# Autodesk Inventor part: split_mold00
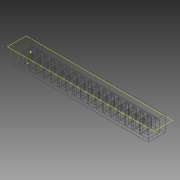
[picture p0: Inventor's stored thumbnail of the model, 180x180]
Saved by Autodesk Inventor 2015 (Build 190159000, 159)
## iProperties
Created: 2015-04
Part Number: split_mold00
Material: Generic
Document SubType Name: Modeling
Designer: sungeun
Density: 1 g/cm^3
Appearance: Default
Author: sungeun
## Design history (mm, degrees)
sketch "Sketch1"
  geometry: L1 (-4, -7.5)-(4, -7.5); L2 (4, -7.5)-(4, 7.5); L3 (4, 7.5)-(-4, 7.5); L4 (-4, 7.5)-(-4, -7.5); L5 (-4, -7.5)-(4, 7.5); L6 (4, -7.5)-(-4, 7.5); 1 further point
  constraints: 12 end point, 2 midpoint, 2 parallel, 1 horizontal, 1 perpendicular
  dimensions: "d0" = 8 distance of L3.end L2.end; "d1" = 15 distance of L2.end L1.end
extrude "Extrusion1" new body sketch "Sketch1" distance "d2" = 15; taper "d3" = 0 deg
sketch "Sketch2"
  geometry: L1 (-3, 5.5)-(3, 5.5); L2 (3, 5.5)-(3, -5.5); L3 (3, -5.5)-(-3, -5.5); L4 (-3, -5.5)-(-3, 5.5); L5 (4, -7.5)-(4, 7.5) reference; L6 (-4, 7.5)-(-4, -7.5) reference; L7 (4, 7.5)-(-4, 7.5) reference; L8 (-4, -7.5)-(4, -7.5) reference; 1 further point
  constraints: 8 end point, 2 parallel, 1 horizontal, 1 perpendicular
  dimensions: "d4" = 1 distance between parallel lines of L5 L2; "d5" = 1 distance between parallel lines of L6 L4; "d6" = 2 distance between parallel lines of L7 L1; "d7" = 2 distance between parallel lines of L8 L3
extrude "Extrusion2" cut sketch "Sketch2" distance "d8" = 13; taper "d9" = 0 deg
sketch "Sketch3"
  geometry: L1 (0, 15)-(-15, 15) reference; L2 (-15, 0)-(-12, 0); L3 (-12, 0)-(-12, 15); L4 (-12, 15)-(-15, 15); L5 (-15, 15)-(-15, 0); L6 (-15, 0)-(-15, 15) reference; 2 further points
  constraints: 8 end point, 2 midpoint, 2 parallel, 1 coincident, 1 horizontal, 1 perpendicular, 1 point on line
  dimensions: "d17" = 3 distance of L2.start L2.end; "d18" = 15 distance of L2.end L3.end
extrude "Extrusion3" join sketch "Sketch3" distance "d11" = 2; taper "d12" = 0 deg
pattern_linear "Rectangular Pattern1"
sketch "Sketch4"
  geometry: L1 (0, 15)-(-12, 15); L2 (-12, 15)-(-12, 0); L3 (-12, 0)-(0, 0); L4 (0, 0)-(0, 15); 1 further point
  constraints: 8 end point, 2 parallel, 1 horizontal, 1 perpendicular
extrude "Extrusion4" join sketch "Sketch4" distance "d19" = 2; taper "d20" = 0 deg
sketch "Sketch5"
  geometry: 1 further point
sketch "Sketch6"
  geometry: L1 (0, 0)-(15, 0); L2 (15, 0)-(15, 15); L3 (15, 15)-(0, 15); L4 (0, 15)-(0, 0); 1 further point
  constraints: 8 end point, 2 parallel, 1 horizontal, 1 perpendicular
  dimensions: "d21" = 15 distance of L3.end L1.start; "d22" = 15 distance of L2.end L3.end
extrude "Extrusion5" join sketch "Sketch6" distance "d23" = 2; taper "d24" = 0 deg
sketch "Sketch7"
  geometry: 1 further point
sketch "Sketch8"
  geometry: L1 (3, 5.5)-(3, -5.5) reference; L2 (157, -5.5)-(157, 5.5) reference; L3 (3, 1)-(157, 1); L4 (157, 1)-(157, -1); L5 (157, -1)-(3, -1); L6 (3, -1)-(3, 1); 3 further points
  constraints: 8 end point, 2 midpoint, 2 parallel, 2 point on line, 1 coincident, 1 horizontal, 1 perpendicular
  dimensions: "d25" = 2 distance between parallel lines of L5 L3
extrude "Extrusion6" cut sketch "Sketch8" distance "d26" = 2; taper "d27" = 0 deg
sketch "Sketch9"
  geometry: L1 (-3, 5.5)-(163, 5.5); L2 (163, 5.5)-(163, -5.5); L3 (163, -5.5)-(-3, -5.5); L4 (-3, -5.5)-(-3, 5.5); L5 (164, 6.5)-(-4, 6.5); L6 (-4, 6.5)-(-4, -6.5); L7 (-4, -6.5)-(164, -6.5); L8 (164, -6.5)-(164, 6.5)
  constraints: 16 end point, 4 parallel, 2 perpendicular, 1 horizontal, 3 other
  dimensions: "d29" = 1 distance between parallel lines of L1 L5
extrude "Extrusion7" join sketch "Sketch9" distance "d30" = 2; taper "d31" = 0 deg
sketch "Sketch10"
  geometry: L1 (-3, 5.5)-(163, 5.5) reference; L2 (7, 5.5)-(3, 5.5); L3 (3, 5.5)-(3, 1); L4 (3, 1)-(7, 1); L5 (7, 1)-(7, 5.5); L6 (163, -5.5)-(-3, -5.5) reference; L7 (7, -1)-(3, -1); L8 (3, -1)-(3, -5.5); L9 (3, -5.5)-(7, -5.5); L10 (7, -5.5)-(7, -1); L11 (6, 4.5)-(4, 4.5); L12 (4, 4.5)-(4, 2); L13 (4, 2)-(6, 2); L14 (6, 2)-(6, 4.5); L15 (6, -2)-(4, -2); L16 (4, -2)-(4, -4.5); L17 (4, -4.5)-(6, -4.5); L18 (6, -4.5)-(6, -2); 3 further points
  constraints: 32 end point, 8 parallel, 4 perpendicular, 2 horizontal, 2 midpoint, 2 point on line, 1 vertical alignment, 6 other
  dimensions: "d32" = 4 distance between parallel lines of L3 L5; "d33" = 4 distance between parallel lines of L8 L10; "d34" = 4.5 distance of L7.end L8.end; "d35" = 1 distance between parallel lines of L5 L14; "d36" = 1 distance between parallel lines of L10 L18
extrude "Extrusion8" join sketch "Sketch10" distance "d37" = 2; taper "d38" = 0 deg
pattern_linear "Rectangular Pattern2" dims "d41" = 10
sketch "Sketch11"
  geometry: L1 (10, -11.5)-(-170, -11.5); L2 (-170, -11.5)-(-170, 11.5); L3 (-170, 11.5)-(10, 11.5); L4 (10, 11.5)-(10, -11.5); L5 (-156, 7.5)-(-166, 7.5) reference; L6 (-116, -7.5)-(-124, -7.5) reference; L7 (-166, -7.5)-(-166, 7.5) reference; L8 (6, 7.5)-(6, -7.5) reference; 1 further point
  constraints: 8 end point, 2 parallel, 1 horizontal, 1 perpendicular
  dimensions: "d42" = 4 distance between parallel lines of L3 L5; "d43" = 4 distance between parallel lines of L6 L1; "d44" = 4 distance between parallel lines of L2 L7; "d45" = 4 distance between parallel lines of L4 L8
extrude "Extrusion9" new body sketch "Sketch11" distance "d46" = 21; taper "d47" = 0 deg
combine "Combine1"
  body "Solid1"
workplane "Work Plane2"
body "Solid2"
